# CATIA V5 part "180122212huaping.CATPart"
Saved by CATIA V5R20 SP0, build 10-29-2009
Part number: huaping22212
Material "Water": density 1000 kg/m3
Bounding box of the stored display mesh (mm): x -50.191 to 50.191, y -71.784 to 49.937, z 0 to 178.355
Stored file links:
  G:\huaping22212.CATPart
  D:\Catia\win_b64\startup\materials\Catalog.CATMaterial
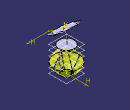
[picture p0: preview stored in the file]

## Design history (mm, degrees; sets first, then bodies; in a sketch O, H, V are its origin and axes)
Body1 (main body)
  Plane1: type Offset, RefPlane xy-plane, Offset 20
  Plane2: type Offset, RefPlane Plane1, Offset 20
  Plane3: type Offset, RefPlane Plane2, Offset 20
  Plane4: type Offset, RefPlane Plane3, Offset 20
  Plane5: type Offset, RefPlane Plane4, Offset 20
  Sketch1 on xy-plane, origin (0, 0, 0), H (1, 0, 0), V (0, 1, 0)
    point P1 (0, 30)
    circle A1 centre (0, 0) radius 20
    point P2 (0, 20)
    radius A1 = 20
    coincidence: P1 V, A1 P2, P2 V
  Sketch2 on Plane1, origin (0, 0, 20), H (1, 0, 0), V (0, 1, 0)
    circle A1 centre (0, 0) radius 40
    radius A1 = 40
  Sketch3 on Plane2, origin (0, 0, 40), H (1, 0, 0), V (0, 1, 0)
    circle A1 centre (0, 0) radius 50
    point P1 (0, 50)
    radius A1 = 50
    coincidence: A1 P1, P1 V
  Sketch4 on Plane3, origin (0, 0, 60), H (1, 0, 0), V (0, 1, 0)
    circle A1 centre (0, 0) radius 40
    point P1 (0, 40)
    radius A1 = 40
    coincidence: A1 P1, P1 V
  Sketch5 on Plane4, origin (0, 0, 80), H (1, 0, 0), V (0, 1, 0)
    circle A1 centre (0, 0) radius 20
    point P1 (0, 20)
    radius A1 = 20
    coincidence: A1 P1, P1 V
  Sketch6 on Plane5, origin (0, 0, 100), H (1, 0, 0), V (0, 1, 0)
    circle A1 centre (0, 0) radius 30
    radius A1 = 30
  Loft1: solid, Sections (Sketch1; Sketch2; Sketch3; Sketch4; Sketch5; Sketch6)
  Plane6: type Offset, RefPlane Plane4, Offset 20
  Shell1: IntOffset 1, Face face of Loft1, ExtOffset 0
  Sketch7 on xy-plane, origin (0, 0, 0), H (1, 0, 0), V (0, 1, 0)
    point P1 (0, 30)
    circle A1 centre (0, 0) radius 20
    point P2 (0, 20)
    radius A1 = 20
    coincidence: P1 V, A1 P2, P2 V
  Sketch8 on Plane1, origin (0, 0, 20), H (1, 0, 0), V (0, 1, 0)
    circle A1 centre (0, 0) radius 40
    radius A1 = 40
  Sketch9 on Plane2, origin (0, 0, 40), H (1, 0, 0), V (0, 1, 0)
    circle A1 centre (0, 0) radius 50
    point P1 (0, 50)
    radius A1 = 50
    coincidence: A1 P1, P1 V
  Sketch10 on Plane3, origin (0, 0, 60), H (1, 0, 0), V (0, 1, 0)
    circle A1 centre (0, 0) radius 40
    point P1 (0, 40)
    radius A1 = 40
    coincidence: A1 P1, P1 V
  Sketch11 on Plane4, origin (0, 0, 80), H (1, 0, 0), V (0, 1, 0)
    circle A1 centre (0, 0) radius 20
    point P1 (0, 20)
    radius A1 = 20
    coincidence: A1 P1, P1 V
  Sketch12 on Plane5, origin (0, 0, 100), H (1, 0, 0), V (0, 1, 0)
    circle A1 centre (0, 0) radius 30
    radius A1 = 30
  Loft2: solid, Sections (Sketch7; Sketch8; Sketch9; Sketch10; Sketch11; Sketch12)
  Sketch13 on xy-plane, origin (0, 0, 0), H (1, 0, 0), V (0, 1, 0)
    point P1 (0, 30)
    circle A1 centre (0, 0) radius 20
    point P2 (0, 20)
    radius A1 = 20
    coincidence: P1 V, A1 P2, P2 V
  Sketch14 on Plane1, origin (0, 0, 20), H (1, 0, 0), V (0, 1, 0)
    circle A1 centre (0, 0) radius 40
    radius A1 = 40
  Sketch15 on Plane2, origin (0, 0, 40), H (1, 0, 0), V (0, 1, 0)
    circle A1 centre (0, 0) radius 50
    point P1 (0, 50)
    radius A1 = 50
    coincidence: A1 P1, P1 V
  Sketch16 on Plane3, origin (0, 0, 60), H (1, 0, 0), V (0, 1, 0)
    circle A1 centre (0, 0) radius 40
    point P1 (0, 40)
    radius A1 = 40
    coincidence: A1 P1, P1 V
  Sketch17 on Plane4, origin (0, 0, 80), H (1, 0, 0), V (0, 1, 0)
    circle A1 centre (0, 0) radius 20
    point P1 (0, 20)
    radius A1 = 20
    coincidence: A1 P1, P1 V
  Sketch18 on Plane5, origin (0, 0, 100), H (1, 0, 0), V (0, 1, 0)
    circle A1 centre (0, 0) radius 30
    radius A1 = 30
  Loft3: solid, Sections (Sketch13; Sketch14; Sketch15; Sketch16; Sketch17; Sketch18)
Body2, material "Water"
  Sketch19 on yz-plane, origin (0, 0, 0), H (0, 1, 0), V (0, 0, 1)
    point P1 (0, 40.6091)
    line L1 (0, 40.6091) -> (49.7433, 40.6091)
    arc A1 centre (-19.2519, 61.0676) radius 71.9645 from (49.7433, 40.6091) to (18.8222, 0) cw
    point P4 (18.8222, 0)
    line L2 (18.8222, 0) -> (0, 0)
    line L3 (0, 0) -> (0, 40.6091)
    coincidence: P1 V, P4 H
    horizontal: L1 H, L2 H
    vertical: L3 V
  Groove1: profile Sketch19, axis Sketch19.L3, angle 360
Body3
  Sketch20 on yz-plane, origin (0, 0, 0), H (0, 1, 0), V (0, 0, 1)
    spline S1 through (-20, 10) (-30, 50) (-10, 80) (-10, 150)
  Plane7: type Normal, Curve Sketch20, RefPoint vertex of Sketch20
  Sketch21 on Plane7, origin (0, -71.7842, 109.4946), H (1, 0, 0), V (0, 0.8363, 0.5483)
    circle A1 centre (0, 73.8781) radius 1
    point P1 (0, 73.8781)
    reference projected point E1 (0, 73.8781) from vertex of Sketch20
    coincidence: P1 E1
  Rib1: profile Sketch21, centre curve Sketch20
Body4
  Sketch22 on Plane7, origin (0, -71.7842, 109.4946), H (1, 0, 0), V (0, 0.8363, 0.5483)
    point P1 (0, 73.8781)
    reference projected point E1 (0, 73.8781) from vertex of Sketch20
    arc A1 centre (0, 103.8781) radius 30 from (0, 73.8781) to (25.9808, 118.8781) ccw
    point P2 (0, 103.8781)
    point P3 (25.9808, 88.8781)
    arc A2 centre (25.9808, 88.8781) radius 30 from (25.9808, 118.8781) to (0, 73.8781) ccw
    coincidence: P1 E1, A1 P1, P2 V, P3 A1, A2 P1
  Pad1: profile Sketch22, direction (0, -0.5483, 0.8363), length 1
  CircPattern1: of Pad1, instances 8, angular step 45, axis from Plane7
